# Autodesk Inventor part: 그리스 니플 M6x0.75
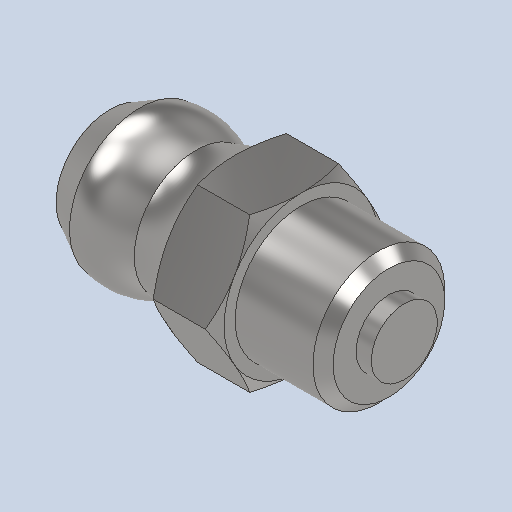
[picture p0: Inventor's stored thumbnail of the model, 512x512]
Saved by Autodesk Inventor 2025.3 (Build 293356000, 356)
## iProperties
Created: 2025-10
Part Number: 그리스 니플 M6x0.75
Material: 강철, 연강
Description: 윤활 니플, 원추 유형 A
Document SubType Name: Modeling
Designer: USER
Density: 7.85 g/cm^3
Appearance: 기본값
Sending System: Autodesk Inventor 2026
Preprocessor: ST-DEVELOPER v20.1
Author: jhkim
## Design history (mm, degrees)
feature "Solid1"
node "솔리드1"
